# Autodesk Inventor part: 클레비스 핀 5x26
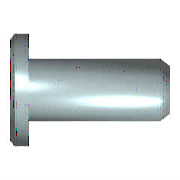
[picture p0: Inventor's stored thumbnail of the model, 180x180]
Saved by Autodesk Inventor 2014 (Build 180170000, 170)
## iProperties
IsCustomPart: 0
Created: 2012-02
Part Number: 클레비스 핀 5x26
Material: 강철
Description: 머리가 있는 클레비스 핀
Document SubType Name: Modeling
Standard: ISO 2341
Designer: mduedu
Standard Revision: Second edition 1986-11-01
Standards Organization: ISO
Language: ko-KR
Size Designation: A - 5 x 26
Categories: <MemberInstance><Categories><Category DisplayName="조임쇠" InternalName="e4da775c-781d-43d5-af7c-5136215cf5a6" Mnemonic="FSTN"><Category DisplayName="핀" InternalNa
Density: 7.85 g/cm^3
Mass: 4.39173 g
Surface Area: 5.28965 cm^2
Volume: 0.559456 cm^3
Appearance: 노란색
Author: mduedu
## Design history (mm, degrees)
sketch "스케치1"
  geometry: L1 (-1.6, 0)-(-1.6, 4); L2 (-1.6, 4)-(0, 4); L3 (0, 4)-(0, 2.5); L4 (0, 2.5)-(26, 2.5); L5 (26, 2.5)-(26, 0); L6 (-1.6, 0)-(26, 0); L7 (-4, 0)-(17, 0) reference; L8 (0, -0.5)-(0, 3) reference
  constraints: 12 end point, 3 parallel, 2 collinear, 2 perpendicular, 1 vertical
  dimensions: "d0" = 1.6 distance of L1.end L2.end (= KOH); "d1" = 26 distance of L3.end L4.end (= NLG); "d2" = 5 diameter of L4 L6 (= NND); "d3" = 8 diameter of L2 L6 (= KOD)
revolve "본체" sketch "스케치1" stored, may be unused: angle "d5" = 90 deg
node "작업 평면1"
sketch "스케치2"
  geometry: C1 r 2.5 at (0, 0) reference; C2 r 1.95 at (0, 0); 1 further point
  constraints: 1 centre point, 1 coincident
  dimensions: "d16" = 3.9 diameter of C2
extrude "돌출1" cut sketch "스케치2" distance "d17" = 0.6; taper "d18" = 0 deg
body "Solid1"
chamfer "모따기1" distance "d7" = 2 (= PHH1); stored, may be unused: angle "d8" = 30 deg (= FAWI1), second distance "d12" = 2 (= PHH1)
chamfer "모따기2" distance "d4" = 1 (= PHH2); stored, may be unused: angle "d6" = 45 deg (= FAWI2), second distance "d13" = 1 (= PHH2)
other parameters: "NLG" = 26 [user parameter; used in 1 equation term], "KOH" = 1.6 [user parameter; used in 1 equation term], "KOD" = 8 [user parameter; used in 1 equation term], "NND" = 5 [user parameter; used in 1 equation term], "FAWI1" = 30 deg [user parameter; used in 1 equation term], "FAWI2" = 45 deg [user parameter; used in 1 equation term], "PHH2" = 1 [user parameter; used in 2 equation terms], "PHH1" = 2 [user parameter; used in 2 equation terms], "d9" = 0, "d10" = 0, "d14" = 0, "d15" = 21
